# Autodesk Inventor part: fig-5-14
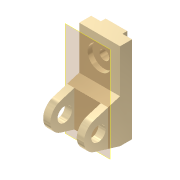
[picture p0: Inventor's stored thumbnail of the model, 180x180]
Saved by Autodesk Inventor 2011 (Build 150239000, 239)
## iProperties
Shininess: 65.0
Angle Display Precision: 2
Document Length Units: 11269
Document Angle Units: 11279
Document Time Units: 11290
Document Mass Units: 11283
Document Length Units Precision: 3
Document Angle Units Precision: 2
Compacted: False
Created: 2001-11
Part Number: fig-5-14
Document SubType Name: Modeling
Designer: Renu Muthoo
Density: 1 g/cm^3
Density: 0.0
Volumn: 0.0
Area: 0.0
PropertySet Name: Model Information
Control State: 0
Master: False
Checked Out: False
Author: Renu Muthoo
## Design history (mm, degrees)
node "Sketch1"
sketch "Sketch2"
  geometry: L1 (33.257, 104.664)-(33.257, -75.336); L2 (33.257, -75.336)-(8.257, -75.336); L3 (8.257, -75.336)-(-45.451, -59.045); L4 (-45.451, -1.628)-(8.257, 14.664); L5 (8.257, 14.664)-(8.257, 104.664); L6 (8.257, 104.664)-(33.257, 104.664); C1 r 15 at (-36.743, -30.336); A1 r 30 centre (-36.743, -30.336) between (-45.451, -1.628) and (-45.451, -59.045)
  constraints: 12 end point, 2 centre point, 2 equal length, 2 parallel, 2 point on circle, 2 tangent, 1 coincident, 1 perpendicular, 1 vertical
  dimensions: "d0" = 180 distance of L1.start L1.end; "d1" = 30 radius of A1; "d2" = 25 distance of L5.end L1.start; "d3" = 45 distance from line of L2 A1.centre; "d4" = 70 distance from line of L1 A1.centre; "d5" = 30 diameter of C1
extrude "Extrusion1" new body sketch "Sketch2" distance "d6" = 85; taper "d7" = 0 deg
workplane "Work Plane1"
sketch "Sketch3"
  geometry: L1 (15, 62.364)-(70, 62.364); L2 (70, 62.364)-(70, -52.386); L3 (70, -52.386)-(15, -52.386); L4 (15, -52.386)-(15, 62.364); L5 (0, -45)-(0, -28.708) reference
  constraints: 8 end point, 2 parallel, 1 horizontal, 1 perpendicular
  dimensions: "d8" = 55 distance of L1.start L1.end; "d9" = 15 distance between parallel lines of L5 L4
extrude "Extrusion2" cut sketch "Sketch3" distance "d10" = 50; taper "d11" = 0 deg
sketch "Sketch4"
  geometry: L1 (0, 25)-(85, 25) reference; L2 (0, 0)-(0, 25) reference; L3 (20, 25)-(65, 25); L4 (65, 25)-(65, 35); L5 (65, 35)-(20, 35); L6 (20, 35)-(20, 25)
  constraints: 8 end point, 2 parallel, 1 horizontal, 1 perpendicular, 1 point on line
  dimensions: "d12" = 45 distance of L4.end L5.end; "d13" = 10 distance of L3.end L4.end; "d14" = 20 distance between parallel lines of L2 L6
extrude "Extrusion3" join sketch "Sketch4" stored distance "d15" = 50; taper "d16" = 0 deg
sketch "Sketch5"
  geometry: L1 (85, 0)-(85, 90) reference; L2 (0, 90)-(85, 90) reference; 1 further point
  dimensions: "d17" = 42 distance from line of L2 point (42.5, 48); "d18" = 42.5 distance from line of L1 point (42.5, 48)
hole "Hole1" sketch "Sketch5" at (42.5, 48) diameter "d19" = 20; stored, may be unused: countersink angle "d23" = 82 deg, drill point angle "d25" = 118 deg; dims "d20" = 6, "d21" = 50, "d22" = 10, "d24" = 8
workplane "Work Plane6"
body "Solid1"
other parameters: "d26" = 0
